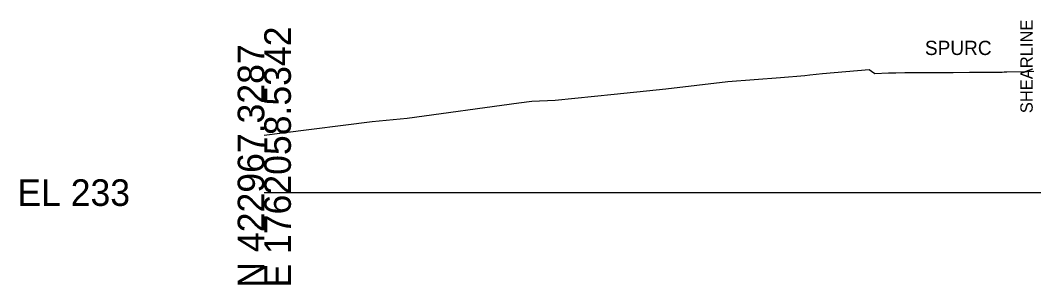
# Model space of a CAD drawing. Extents: x -26 to 3203, y -11010 to 4024.
# Drawn here: x -25.7 to 81, y -3009.7 to -2981.9 of the extents above; entities that cross this region are included whole.
import ezdxf

# ---------------------------------------------------------------- set-up
doc = ezdxf.new("R2010")
doc.units = 0
for name, color, linetype in [('Default', 7, 'Continuous'), ('Exist Cross Section Cell', 7, 'Continuous'), ('Exist XS Ground Line', 7, 'Continuous'), ('Prop CMT Shear Line Text', 7, 'Continuous'), ('Prop XS SE Text', 7, 'Continuous')]:
    doc.layers.add(name, color=color, linetype=linetype)

msp = doc.modelspace()

# ---------------------------------------------------------------- linework, layer by layer
at = {"layer": 'Exist Cross Section Cell'}
msp.add_line((0, -3000), (100, -3000), dxfattribs=at)
at = {"layer": 'Exist XS Ground Line'}
msp.add_lwpolyline([(0, -2993.96), (1.92, -2993.71), (11.34, -2992.51), (15.03, -2992.17), (26.81, -2990.55), (28.15, -2990.38), (30.61, -2990.28), (36.83, -2989.64), (41.24, -2989.18), (42.28, -2989.09), (48.81, -2988.32), (54.35, -2987.89), (56.92, -2987.66), (57.44, -2987.6), (58.76, -2987.48), (63.67, -2987.03), (63.94, -2987.21), (64.27, -2987.47), (65.72, -2987.4), (66.13, -2987.38), (66.17, -2987.38), (66.49, -2987.38), (67.45, -2987.37), (68.33, -2987.37), (68.49, -2987.37), (70.37, -2987.36), (70.69, -2987.36), (71, -2987.36), (72.53, -2987.35), (74.25, -2987.33), (74.37, -2987.33), (76, -2987.31), (77.69, -2987.31), (77.91, -2987.3), (78.16, -2987.3), (80.12, -2987.26), (80.27, -2987.25), (81.03, -2987.22)], dxfattribs=at)
msp.add_lwpolyline([(0, -2993.96), (1.92, -2993.71), (11.34, -2992.51), (15.03, -2992.17), (26.81, -2990.55), (28.15, -2990.38), (30.61, -2990.28), (36.83, -2989.64), (41.24, -2989.18), (42.28, -2989.09), (48.81, -2988.32), (54.35, -2987.89), (56.92, -2987.66), (57.44, -2987.6), (58.76, -2987.48), (63.67, -2987.03), (63.94, -2987.21), (64.27, -2987.47), (65.72, -2987.4), (66.13, -2987.38), (66.17, -2987.38), (66.49, -2987.38), (67.45, -2987.37), (68.33, -2987.37), (68.49, -2987.37), (70.37, -2987.36), (70.69, -2987.36), (71, -2987.36), (72.53, -2987.35), (74.25, -2987.33), (74.37, -2987.33), (76, -2987.31), (77.69, -2987.31), (77.91, -2987.3), (78.16, -2987.3), (80.12, -2987.26), (80.27, -2987.25), (81.03, -2987.22)], dxfattribs=at)
msp.add_lwpolyline([(0, -2993.96), (1.92, -2993.71), (11.34, -2992.51), (15.03, -2992.17), (26.81, -2990.55), (28.15, -2990.38), (30.61, -2990.28), (36.83, -2989.64), (41.24, -2989.18), (42.28, -2989.09), (48.81, -2988.32), (54.35, -2987.89), (56.92, -2987.66), (57.44, -2987.6), (58.76, -2987.48), (63.67, -2987.03), (63.94, -2987.21), (64.27, -2987.47), (65.72, -2987.4), (66.13, -2987.38), (66.17, -2987.38), (66.49, -2987.38), (67.45, -2987.37), (68.33, -2987.37), (68.49, -2987.37), (70.37, -2987.36), (70.69, -2987.36), (71, -2987.36), (72.53, -2987.35), (74.25, -2987.33), (74.37, -2987.33), (76, -2987.31), (77.69, -2987.31), (77.91, -2987.3), (78.16, -2987.3), (80.12, -2987.26), (80.27, -2987.25), (81.03, -2987.22)], dxfattribs=at)
msp.add_lwpolyline([(0, -2993.96), (1.92, -2993.71), (11.34, -2992.51), (15.03, -2992.17), (26.81, -2990.55), (28.15, -2990.38), (30.61, -2990.28), (36.83, -2989.64), (41.24, -2989.18), (42.28, -2989.09), (48.81, -2988.32), (54.35, -2987.89), (56.92, -2987.66), (57.44, -2987.6), (58.76, -2987.48), (63.67, -2987.03), (63.94, -2987.21), (64.27, -2987.47), (65.72, -2987.4), (66.13, -2987.38), (66.17, -2987.38), (66.49, -2987.38), (67.45, -2987.37), (68.33, -2987.37), (68.49, -2987.37), (70.37, -2987.36), (70.69, -2987.36), (71, -2987.36), (72.53, -2987.35), (74.25, -2987.33), (74.37, -2987.33), (76, -2987.31), (77.69, -2987.31), (77.91, -2987.3), (78.16, -2987.3), (80.12, -2987.26), (80.27, -2987.25), (81.03, -2987.22)], dxfattribs=at)
msp.add_lwpolyline([(0, -2993.96), (1.92, -2993.71), (11.34, -2992.51), (15.03, -2992.17), (26.81, -2990.55), (28.15, -2990.38), (30.61, -2990.28), (36.83, -2989.64), (41.24, -2989.18), (42.28, -2989.09), (48.81, -2988.32), (54.35, -2987.89), (56.92, -2987.66), (57.44, -2987.6), (58.76, -2987.48), (63.67, -2987.03), (63.94, -2987.21), (64.27, -2987.47), (65.72, -2987.4), (66.13, -2987.38), (66.17, -2987.38), (66.49, -2987.38), (67.45, -2987.37), (68.33, -2987.37), (68.49, -2987.37), (70.37, -2987.36), (70.69, -2987.36), (71, -2987.36), (72.53, -2987.35), (74.25, -2987.33), (74.37, -2987.33), (76, -2987.31), (77.69, -2987.31), (77.91, -2987.3), (78.16, -2987.3), (80.12, -2987.26), (80.27, -2987.25), (81.03, -2987.22)], dxfattribs=at)

# ---------------------------------------------------------------- texts
at = {"layer": 'Default'}
msp.add_text('-', height=0.0001, dxfattribs=at).set_placement((0, -3000))
at = {"layer": 'Exist Cross Section Cell'}
for s, p in [('E 1762058.5342', (2.8, -3010)), ('N 422967.3287', (0, -3010))]:
    msp.add_text(s, height=2.8, rotation=90, dxfattribs=at).set_placement(p)
msp.add_text('EL 233', height=2.8, dxfattribs=at).set_placement((-26, -3001.4))
at = {"layer": 'Prop CMT Shear Line Text'}
msp.add_text('SHEARLINE', height=1.3, rotation=90, dxfattribs=at).set_placement((80.9, -2991.64))
msp.add_text('SHEARLINE', height=1.3, rotation=90, dxfattribs=at).set_placement((80.9, -2991.64))
at = {"layer": 'Prop XS SE Text'}
msp.add_text('SPURC', height=1.5, rotation=360, dxfattribs=at).set_placement((69.55, -2985.52))

doc.saveas('drawing.dxf')
